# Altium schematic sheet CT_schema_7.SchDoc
size 235 x 258 mm
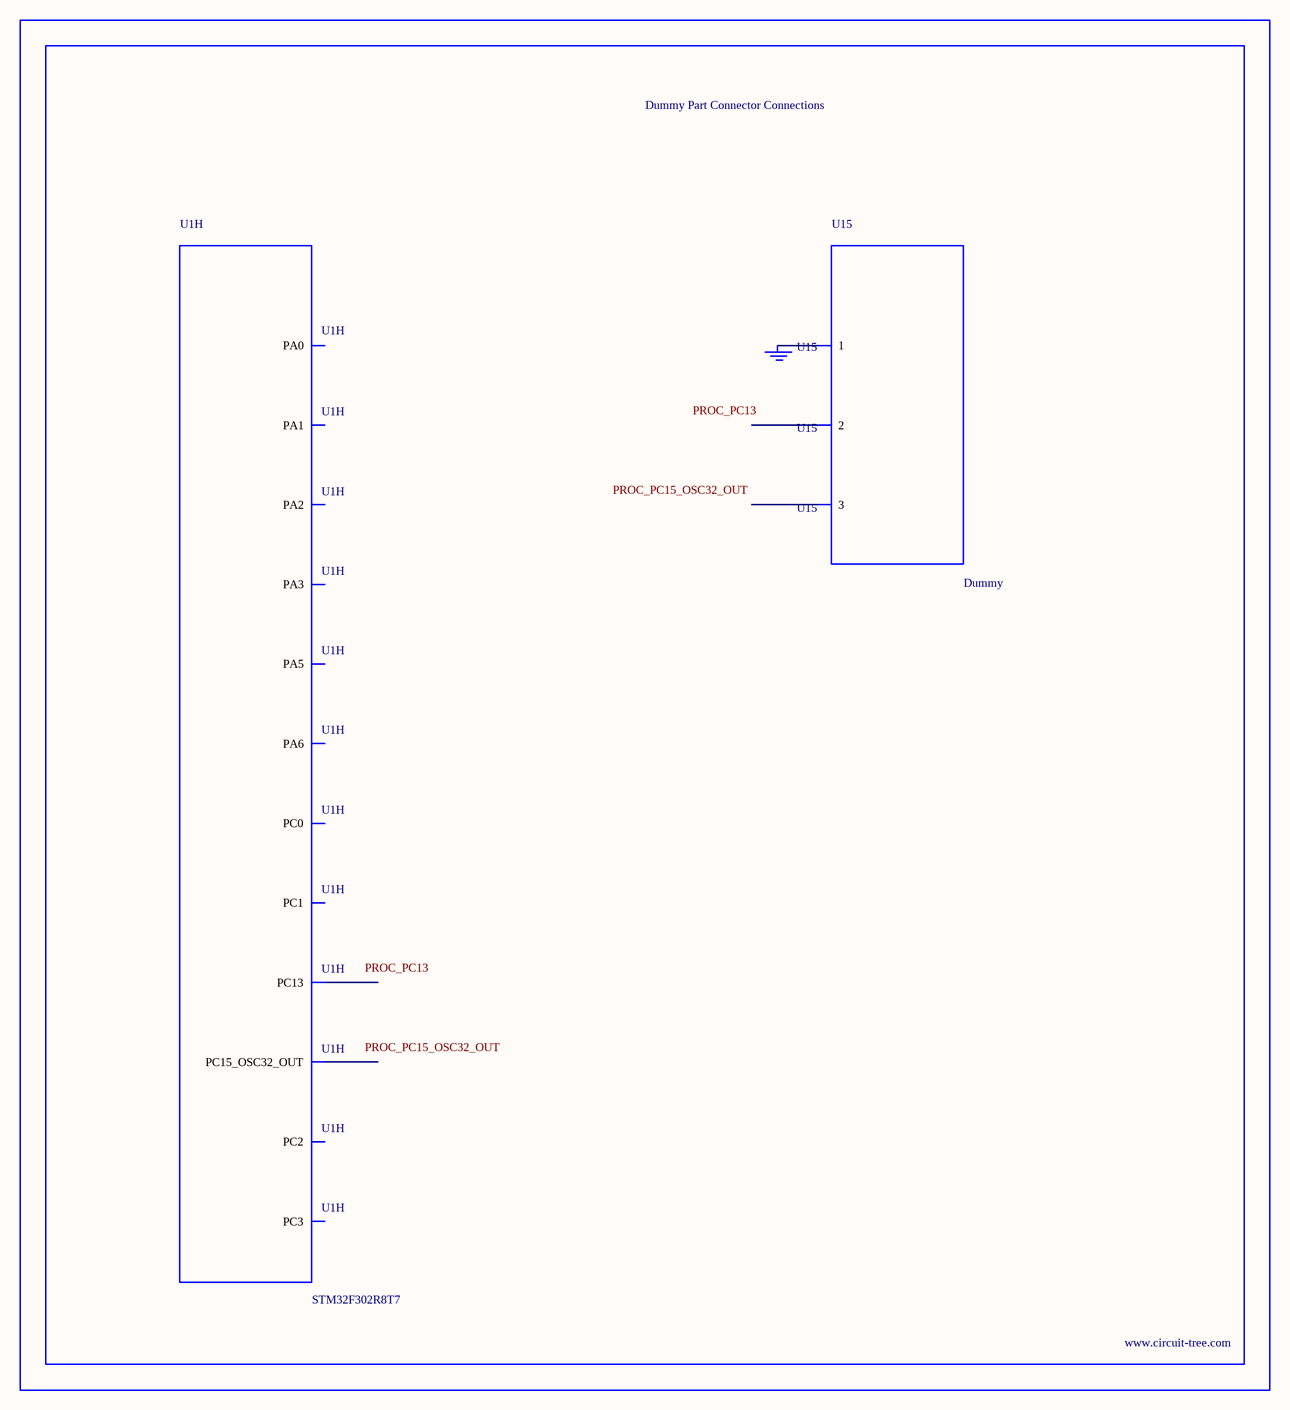
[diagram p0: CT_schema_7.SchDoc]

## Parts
BORDER6  (no value)
GND_INSTANCE_6_0  (no value)
U1  STM32F302R8T7  [LQFP64]  (part H of 8)
U15  Dummy  [DUMMY_PACKAGE_160]

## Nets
NetGND_INSTANCE_6_0_0: GND_INSTANCE_6_0.0(GND) U15.1

Not connected (* = marked no-connect by the designer): U1 2(PC13) 4(PC15_OSC32_OUT) 8(PC0) 9(PC1) 10(PC2) 11(PC3) 14(PA0) 15(PA1) 16(PA2) 17(PA3) 21(PA5) 22(PA6); U15 2 3

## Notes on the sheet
- Labels drawn without touching a wire or pin: PROC_PC13, PROC_PC15_OSC32_OUT

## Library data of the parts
BORDER6 = BORDER_PAGE6
GND_INSTANCE_6_0 = GND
